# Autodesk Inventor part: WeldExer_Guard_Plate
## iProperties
Created: 2005-02
Part Number: WeldExer_Guard_Plate
Document SubType Name: Modeling
Designer: Dale Schneider
Manufacturer: Standard
Standards Organization: Custom
Stock Number: WeldExer_Guard_Plate
Density: 1 g/cm^3
Author: Dale Schneider
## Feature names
1. Extrusion1
